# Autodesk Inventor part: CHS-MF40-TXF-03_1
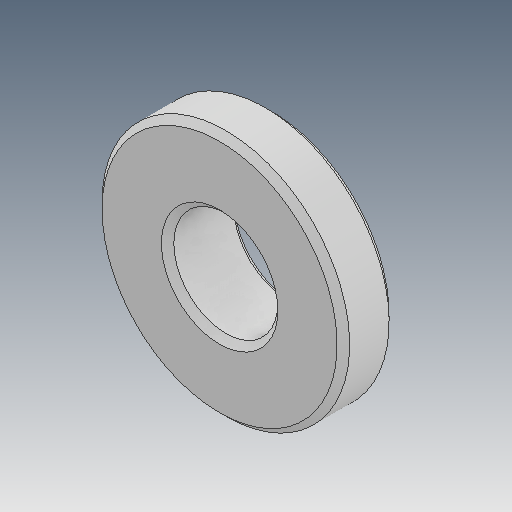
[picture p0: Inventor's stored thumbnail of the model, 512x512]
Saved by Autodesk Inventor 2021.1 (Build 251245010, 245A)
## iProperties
Created: 2019-04
Part Number: CHS-MF40-TXF-03_1
Material: Ogólny
Document SubType Name: Modeling
Designer: user
Density: 1 g/cm^3
Appearance: Domyślna
Author: user
Revision Number: ÈÎºÎ
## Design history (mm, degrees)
feature "ÊäÈë1"
node "Bryła1"
